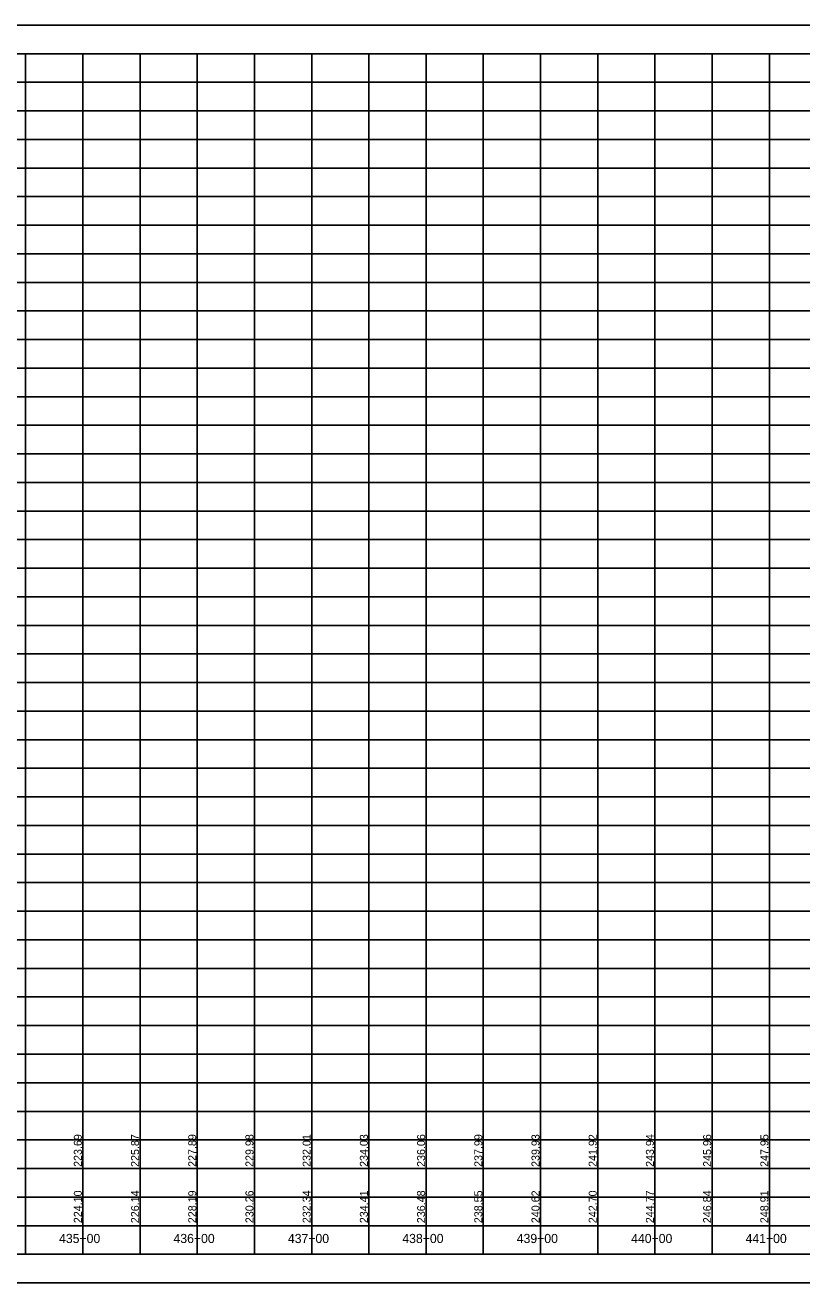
# Model space of a CAD drawing. Extents: x 1873632 to 1926512, y 813126 to 836257.
# Drawn here: x 1921813 to 1922491, y 828238 to 829338 of the extents above; entities that cross this region are included whole.
import ezdxf

# ---------------------------------------------------------------- set-up
doc = ezdxf.new("R2010")
doc.units = 0
for name, color, linetype in [('RD_DDB_StaTX', 7, 'Continuous'), ('RD_DDB_StripGrade', 7, 'Continuous'), ('RD_PD_WallFill', 7, 'Continuous'), ('RD_SHT_IplotShp', 7, 'Continuous')]:
    doc.layers.add(name, color=color, linetype=linetype)

msp = doc.modelspace()

# ---------------------------------------------------------------- linework, layer by layer
at = {"layer": 'RD_PD_WallFill'}
for p, q in [((1921113, 829313.1), (1926463, 829313.1)), ((1921113, 829313.1), (1922863, 829313.1)), ((1921813, 828263.1), (1921813, 829313.1)), ((1921813, 828263.1), (1921813, 829313.1)), ((1921863, 828263.1), (1921863, 829313.1)), ((1921863, 828263.1), (1921863, 829313.1)), ((1921913, 828263.1), (1921913, 829313.1)), ((1921913, 828263.1), (1921913, 829313.1)), ((1921963, 828263.1), (1921963, 829313.1)), ((1921963, 828263.1), (1921963, 829313.1)), ((1922013, 828263.1), (1922013, 829313.1)), ((1922013, 828263.1), (1922013, 829313.1)), ((1922063, 828263.1), (1922063, 829313.1)), ((1922063, 828263.1), (1922063, 829313.1)), ((1922113, 828263.1), (1922113, 829313.1)), ((1922113, 828263.1), (1922113, 829313.1)), ((1922163, 828263.1), (1922163, 829313.1)), ((1922163, 828263.1), (1922163, 829313.1)), ((1922213, 828263.1), (1922213, 829313.1)), ((1922213, 828263.1), (1922213, 829313.1)), ((1922263, 828263.1), (1922263, 829313.1)), ((1922263, 828263.1), (1922263, 829313.1)), ((1922313, 828263.1), (1922313, 829313.1)), ((1922313, 828263.1), (1922313, 829313.1)), ((1922363, 828263.1), (1922363, 829313.1)), ((1922363, 828263.1), (1922363, 829313.1)), ((1922413, 828263.1), (1922413, 829313.1)), ((1922413, 828263.1), (1922413, 829313.1)), ((1922463, 828263.1), (1922463, 829313.1)), ((1922463, 828263.1), (1922463, 829313.1)), ((1921563, 829288.1), (1926463, 829288.1)), ((1921563, 829288.1), (1926463, 829288.1)), ((1921563, 829263.1), (1926463, 829263.1)), ((1921563, 829238.1), (1926463, 829238.1)), ((1921563, 829213.1), (1926463, 829213.1)), ((1921563, 829188.1), (1926463, 829188.1)), ((1921113, 829163.1), (1926463, 829163.1)), ((1921113, 829138.1), (1926463, 829138.1)), ((1921113, 829113.1), (1926463, 829113.1)), ((1921113, 829088.1), (1926463, 829088.1)), ((1921113, 829063.1), (1926463, 829063.1)), ((1921113, 829038.1), (1926463, 829038.1)), ((1921113, 829013.1), (1926463, 829013.1)), ((1921113, 828988.1), (1926463, 828988.1)), ((1921113, 828963.1), (1926463, 828963.1)), ((1921113, 828938.1), (1926463, 828938.1)), ((1921113, 828913.1), (1926463, 828913.1)), ((1921113, 828888.1), (1926463, 828888.1)), ((1921113, 828863.1), (1926463, 828863.1)), ((1921113, 828838.1), (1926463, 828838.1)), ((1921113, 828813.1), (1926463, 828813.1)), ((1921113, 828788.1), (1926463, 828788.1)), ((1921113, 828763.1), (1926463, 828763.1)), ((1921113, 828738.1), (1926463, 828738.1)), ((1921113, 828713.1), (1926463, 828713.1)), ((1921113, 828688.1), (1926463, 828688.1)), ((1921113, 828663.1), (1926463, 828663.1)), ((1921113, 828638.1), (1926463, 828638.1)), ((1921113, 828613.1), (1926463, 828613.1)), ((1921113, 828588.1), (1926463, 828588.1)), ((1921113, 828563.1), (1926463, 828563.1)), ((1921113, 828538.1), (1926463, 828538.1)), ((1921113, 828513.1), (1926463, 828513.1)), ((1921113, 828488.1), (1926463, 828488.1)), ((1921113, 828463.1), (1926463, 828463.1)), ((1921113, 828438.1), (1926463, 828438.1)), ((1921113, 828413.1), (1926463, 828413.1)), ((1921113, 828388.1), (1926463, 828388.1)), ((1921113, 828363.1), (1926463, 828363.1)), ((1921113, 828338.1), (1926463, 828338.1)), ((1921113, 828313.1), (1926463, 828313.1)), ((1921113, 828288.1), (1926463, 828288.1)), ((1921113, 828263.1), (1926463, 828263.1)), ((1921113, 828263.1), (1926463, 828263.1))]:
    msp.add_line(p, q, dxfattribs=at)
at = {"layer": 'RD_SHT_IplotShp'}
msp.add_lwpolyline([(1921088, 828238.1), (1926488, 828238.1), (1926488, 829338.1), (1921088, 829338.1)], close=True, dxfattribs=at)

# ---------------------------------------------------------------- texts
at = {"layer": 'RD_DDB_StaTX'}
for s, p in [('435+00', (1921842.2, 828272.9)), ('436+00', (1921942.2, 828272.9)), ('437+00', (1922042.2, 828272.9)), ('438+00', (1922142.2, 828272.9)), ('439+00', (1922242.2, 828272.9)), ('440+00', (1922342.2, 828272.9)), ('441+00', (1922442.2, 828272.9))]:
    msp.add_text(s, height=8, dxfattribs=at).set_placement(p)
at = {"layer": 'RD_DDB_StripGrade'}
for s, p in [('223.69', (1921862.1, 828339.5)), ('225.87', (1921912.1, 828339.5)), ('227.89', (1921962.1, 828339.5)), ('229.98', (1922012.1, 828339.5)), ('232.01', (1922062.1, 828339.5)), ('234.03', (1922112.1, 828339.5)), ('236.06', (1922162.1, 828339.5)), ('237.99', (1922212.1, 828339.5)), ('239.93', (1922262.1, 828339.5)), ('241.92', (1922312.1, 828339.5)), ('243.94', (1922362.1, 828339.5)), ('245.96', (1922412.1, 828339.5)), ('247.95', (1922462.1, 828339.5)), ('224.10', (1921862.1, 828290.3)), ('226.14', (1921912.1, 828290.3)), ('228.19', (1921962.1, 828290.3)), ('230.26', (1922012.1, 828290.3)), ('232.34', (1922062.1, 828290.3)), ('234.41', (1922112.1, 828290.3)), ('236.48', (1922162.1, 828290.3)), ('238.55', (1922212.1, 828290.3)), ('240.62', (1922262.1, 828290.3)), ('242.70', (1922312.1, 828290.3)), ('244.77', (1922362.1, 828290.3)), ('246.84', (1922412.1, 828290.3)), ('248.91', (1922462.1, 828290.3))]:
    msp.add_text(s, height=7, rotation=90, dxfattribs=at).set_placement(p)

doc.saveas('drawing.dxf')
